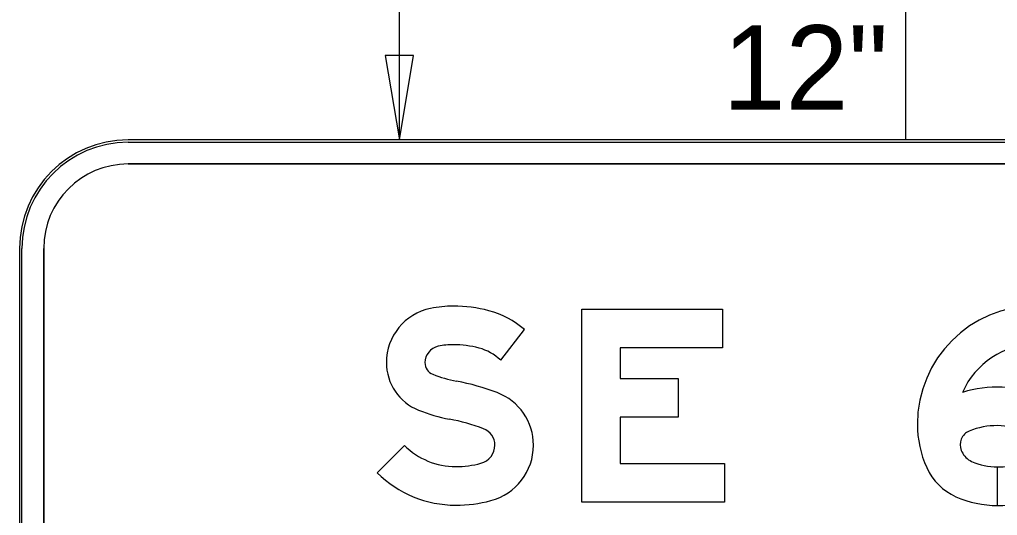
# Model space of a CAD drawing. Extents: x 2149934 to 2150188, y 145113 to 145238.
# Drawn here: x 2150088.03 to 2150094.79, y 145200.85 to 145204.28 of the extents above; entities that cross this region are included whole.
import ezdxf

# ---------------------------------------------------------------- set-up
doc = ezdxf.new("R2010")
doc.units = 0
for name, color, linetype in [('GSBWFILL', 7, 'Continuous'), ('GSCOLORFILL', 7, 'Continuous'), ('GSDIMS', 7, 'Continuous'), ('GSOUTLINE', 7, 'Continuous')]:
    doc.layers.add(name, color=color, linetype=linetype)

msp = doc.modelspace()

# ---------------------------------------------------------------- linework, layer by layer
at = {"layer": 'GSBWFILL'}
for p, q in [((2150107.2786, 145203.4449), (2150088.7786, 145203.4449)), ((2150088.7786, 145203.2782), (2150107.2786, 145203.2782)), ((2150088.0286, 145202.6949), (2150088.0286, 145198.1946)), ((2150088.1953, 145198.1946), (2150088.1953, 145202.6949))]:
    msp.add_line(p, q, dxfattribs=at)
msp.add_lwpolyline([(2150092.8872, 145202.2755), (2150092.8872, 145202.0088), (2150092.1805, 145202.0088), (2150092.1805, 145201.7955), (2150092.5805, 145201.7955), (2150092.5805, 145201.5288), (2150092.1805, 145201.5288), (2150092.1805, 145201.2088), (2150092.9005, 145201.2088), (2150092.9005, 145200.9421), (2150091.9139, 145200.9421), (2150091.9139, 145202.2755)], close=True, dxfattribs=at)
for points in [[(2150091.3539, 145201.9235), (2150091.5188, 145202.134)], [(2150090.6883, 145201.334), (2150090.5005, 145201.1446)], [(2150094.7873, 145200.9188), (2150094.7873, 145201.1855)]]:
    msp.add_lwpolyline(points, dxfattribs=at)
for radius in [0.75, 0.5833]:
    msp.add_arc((2150088.7786, 145202.6949), radius, 90, 180, dxfattribs=at)
for centre, major_axis, ratio, start_param, end_param in [((2150090.9459, 145201.9063), (0, 0.382), 0.999996, 0.202758, 1.570796), ((2150091.0272, 145201.511), (0, 0.7855), 0.999996, 0, 0.202758), ((2150091.0272, 145201.3333), (0, 0.9632), 0.999996, 6.026234, 6.283185), ((2150091.1165, 145201.6734), (0, 0.6115), 0.999996, 5.565152, 6.026234), ((2150095.0519, 145201.4808), (0, 0.818), 0.999998, 0, 1.570796), ((2150090.9459, 145201.9063), (0, 0.1153), 0.999996, 0.202758, 1.570796), ((2150091.0272, 145201.511), (0, 0.5188), 0.999996, 0, 0.202758), ((2150091.0272, 145201.3333), (0, 0.6965), 0.999996, 6.026234, 6.283185), ((2150091.1165, 145201.6734), (0, 0.3448), 0.999996, 5.523837, 6.026234), ((2150095.0519, 145201.4808), (0, 0.5514), 0.999998, 0, 1.161745), ((2150090.9178, 145201.9063), (0, 0.3538), 0.999996, 1.570796, 2.761249), ((2150090.9178, 145201.9063), (0, 0.0872), 0.999996, 1.570796, 2.761249), ((2150091.2084, 145202.6331), (0, 0.8699), 0.999996, 2.761249, 2.95744), ((2150090.7518, 145200.182), (0, 1.6233), 0.999996, 5.918637, 6.099033), ((2150094.783, 145200.9689), (0, 0.7686), 0.999998, 5.875072, 6.596573), ((2150091.1921, 145201.3357), (0, 0.3885), 0.999996, 4.712389, 5.918637), ((2150091.2084, 145202.6331), (0, 1.1366), 0.999996, 2.761249, 2.95744), ((2150090.7518, 145200.182), (0, 1.3566), 0.999996, 5.918637, 6.099033), ((2150091.1921, 145201.3357), (0, 0.1218), 0.999996, 4.712389, 5.918637), ((2150094.9615, 145201.4808), (0, 0.7277), 0.999998, 1.570796, 1.996105), ((2150094.783, 145200.9689), (0, 0.502), 0.999998, 5.875072, 6.672982), ((2150094.6307, 145201.3395), (0, 0.1013), 0.999998, 0.389797, 1.974401), ((2150091.0434, 145201.6923), (0, 0.5044), 0.999996, 2.360607, 3.141593), ((2150091.1844, 145201.3357), (0, 0.1295), 0.999996, 3.401517, 4.712389), ((2150091.1844, 145201.3357), (0, 0.3961), 0.999996, 3.401517, 4.712389), ((2150094.9615, 145201.4808), (0, 0.461), 0.999998, 1.974401, 1.996105), ((2150094.6638, 145201.3459), (0, 0.1341), 0.999998, 1.996105, 2.721836), ((2150091.0434, 145201.866), (0, 0.6782), 0.999996, 3.141593, 3.401517), ((2150094.6638, 145201.3459), (0, 0.4008), 0.999998, 1.996105, 2.721836), ((2150094.7873, 145201.6227), (0, 0.4372), 0.999998, 2.721836, 3.141593), ((2150091.0434, 145201.6923), (0, 0.7711), 0.999996, 2.360607, 3.141593), ((2150094.7873, 145201.6227), (0, 0.7039), 0.999998, 2.721836, 3.141593), ((2150091.0434, 145201.866), (0, 0.9449), 0.999996, 3.141593, 3.401517)]:
    msp.add_ellipse(centre, major_axis=major_axis, ratio=ratio, start_param=start_param, end_param=end_param, dxfattribs=at)
at = {"layer": 'GSCOLORFILL'}
for p, q in [((2150107.2786, 145203.4449), (2150088.7786, 145203.4449)), ((2150107.2786, 145203.4449), (2150088.7786, 145203.4449)), ((2150107.2786, 145203.4449), (2150088.7786, 145203.4449)), ((2150088.7786, 145203.4282), (2150107.2786, 145203.4282)), ((2150088.7786, 145203.2782), (2150107.2786, 145203.2782)), ((2150088.0286, 145202.6949), (2150088.0286, 145198.1946)), ((2150088.0286, 145202.6949), (2150088.0286, 145198.1946)), ((2150088.0286, 145202.6949), (2150088.0286, 145198.1946)), ((2150088.0453, 145198.1946), (2150088.0453, 145202.6949)), ((2150088.1953, 145198.1946), (2150088.1953, 145202.6949))]:
    msp.add_line(p, q, dxfattribs=at)
msp.add_lwpolyline([(2150092.8872, 145202.2755), (2150092.8872, 145202.0088), (2150092.1805, 145202.0088), (2150092.1805, 145201.7955), (2150092.5805, 145201.7955), (2150092.5805, 145201.5288), (2150092.1805, 145201.5288), (2150092.1805, 145201.2088), (2150092.9005, 145201.2088), (2150092.9005, 145200.9421), (2150091.9139, 145200.9421), (2150091.9139, 145202.2755)], close=True, dxfattribs=at)
for points in [[(2150091.3539, 145201.9235), (2150091.5188, 145202.134)], [(2150090.6883, 145201.334), (2150090.5005, 145201.1446)], [(2150094.7873, 145200.9188), (2150094.7873, 145201.1855)]]:
    msp.add_lwpolyline(points, dxfattribs=at)
for radius in [0.75, 0.75, 0.75, 0.7333, 0.5833]:
    msp.add_arc((2150088.7786, 145202.6949), radius, 90, 180, dxfattribs=at)
for centre, major_axis, ratio, start_param, end_param in [((2150090.9459, 145201.9063), (0, 0.382), 0.999996, 0.202758, 1.570796), ((2150091.0272, 145201.511), (0, 0.7855), 0.999996, 0, 0.202758), ((2150091.0272, 145201.3333), (0, 0.9632), 0.999996, 6.026234, 6.283185), ((2150091.1165, 145201.6734), (0, 0.6115), 0.999996, 5.565152, 6.026234), ((2150095.0519, 145201.4808), (0, 0.818), 0.999998, 0, 1.570796), ((2150090.9459, 145201.9063), (0, 0.1153), 0.999996, 0.202758, 1.570796), ((2150091.0272, 145201.511), (0, 0.5188), 0.999996, 0, 0.202758), ((2150091.0272, 145201.3333), (0, 0.6965), 0.999996, 6.026234, 6.283185), ((2150091.1165, 145201.6734), (0, 0.3448), 0.999996, 5.523837, 6.026234), ((2150095.0519, 145201.4808), (0, 0.5514), 0.999998, 0, 1.161745), ((2150090.9178, 145201.9063), (0, 0.3538), 0.999996, 1.570796, 2.761249), ((2150090.9178, 145201.9063), (0, 0.0872), 0.999996, 1.570796, 2.761249), ((2150091.2084, 145202.6331), (0, 0.8699), 0.999996, 2.761249, 2.95744), ((2150090.7518, 145200.182), (0, 1.6233), 0.999996, 5.918637, 6.099033), ((2150094.783, 145200.9689), (0, 0.7686), 0.999998, 5.875072, 6.596573), ((2150091.1921, 145201.3357), (0, 0.3885), 0.999996, 4.712389, 5.918637), ((2150091.2084, 145202.6331), (0, 1.1366), 0.999996, 2.761249, 2.95744), ((2150090.7518, 145200.182), (0, 1.3566), 0.999996, 5.918637, 6.099033), ((2150091.1921, 145201.3357), (0, 0.1218), 0.999996, 4.712389, 5.918637), ((2150094.9615, 145201.4808), (0, 0.7277), 0.999998, 1.570796, 1.996105), ((2150094.783, 145200.9689), (0, 0.502), 0.999998, 5.875072, 6.672982), ((2150094.6307, 145201.3395), (0, 0.1013), 0.999998, 0.389797, 1.974401), ((2150091.0434, 145201.6923), (0, 0.5044), 0.999996, 2.360607, 3.141593), ((2150091.1844, 145201.3357), (0, 0.1295), 0.999996, 3.401517, 4.712389), ((2150091.1844, 145201.3357), (0, 0.3961), 0.999996, 3.401517, 4.712389), ((2150094.9615, 145201.4808), (0, 0.461), 0.999998, 1.974401, 1.996105), ((2150094.6638, 145201.3459), (0, 0.1341), 0.999998, 1.996105, 2.721836), ((2150091.0434, 145201.866), (0, 0.6782), 0.999996, 3.141593, 3.401517), ((2150094.6638, 145201.3459), (0, 0.4008), 0.999998, 1.996105, 2.721836), ((2150094.7873, 145201.6227), (0, 0.4372), 0.999998, 2.721836, 3.141593), ((2150091.0434, 145201.6923), (0, 0.7711), 0.999996, 2.360607, 3.141593), ((2150094.7873, 145201.6227), (0, 0.7039), 0.999998, 2.721836, 3.141593), ((2150091.0434, 145201.866), (0, 0.9449), 0.999996, 3.141593, 3.401517)]:
    msp.add_ellipse(centre, major_axis=major_axis, ratio=ratio, start_param=start_param, end_param=end_param, dxfattribs=at)
at = {"layer": 'GSDIMS'}
for p, q in [((2150090.6535, 145203.4448), (2150090.6535, 145206.4452)), ((2150094.1535, 145203.4448), (2150094.1535, 145204.4451)), ((2150091.091, 145203.4448), (2150090.3618, 145203.4448)), ((2150094.591, 145203.4448), (2150091.091, 145203.4448)), ((2150094.591, 145203.4448), (2150093.8618, 145203.4448))]:
    msp.add_line(p, q, dxfattribs=at)
msp.add_lwpolyline([(2150090.6535, 145203.4448), (2150090.7507, 145204.0281), (2150090.5563, 145204.0281)], close=True, dxfattribs=at)
at = {"layer": 'GSOUTLINE'}
for p, q in [((2150107.2786, 145203.4449), (2150088.7786, 145203.4449)), ((2150107.2786, 145203.2782), (2150088.7786, 145203.2782)), ((2150088.0286, 145202.6949), (2150088.0286, 145198.1946)), ((2150088.1953, 145202.6949), (2150088.1953, 145198.1946))]:
    msp.add_line(p, q, dxfattribs=at)
msp.add_lwpolyline([(2150092.8872, 145202.2755), (2150092.8872, 145202.0088), (2150092.1805, 145202.0088), (2150092.1805, 145201.7955), (2150092.5805, 145201.7955), (2150092.5805, 145201.5288), (2150092.1805, 145201.5288), (2150092.1805, 145201.2088), (2150092.9005, 145201.2088), (2150092.9005, 145200.9421), (2150091.9139, 145200.9421), (2150091.9139, 145202.2755)], close=True, dxfattribs=at)
for points in [[(2150091.3539, 145201.9235), (2150091.5188, 145202.134)], [(2150090.6883, 145201.334), (2150090.5005, 145201.1446)]]:
    msp.add_lwpolyline(points, dxfattribs=at)
for radius in [0.75, 0.5833]:
    msp.add_arc((2150088.7786, 145202.6949), radius, 90, 180, dxfattribs=at)
for centre, major_axis, ratio, start_param, end_param in [((2150090.9459, 145201.9063), (0, 0.382), 0.999996, 0.202758, 1.570796), ((2150091.0272, 145201.511), (0, 0.7855), 0.999996, 0, 0.202758), ((2150091.0272, 145201.3333), (0, 0.9632), 0.999996, 6.026234, 6.283185), ((2150091.1165, 145201.6734), (0, 0.6115), 0.999996, 5.565152, 6.026234), ((2150095.0519, 145201.4808), (0, 0.818), 0.999998, 0, 1.570796), ((2150090.9459, 145201.9063), (0, 0.1153), 0.999996, 0.202758, 1.570796), ((2150091.0272, 145201.511), (0, 0.5188), 0.999996, 0, 0.202758), ((2150091.0272, 145201.3333), (0, 0.6965), 0.999996, 6.026234, 6.283185), ((2150091.1165, 145201.6734), (0, 0.3448), 0.999996, 5.523837, 6.026234), ((2150095.0519, 145201.4808), (0, 0.5514), 0.999998, 0, 1.161745), ((2150090.9178, 145201.9063), (0, 0.3538), 0.999996, 1.570796, 2.761249), ((2150090.9178, 145201.9063), (0, 0.0872), 0.999996, 1.570796, 2.761249), ((2150091.2084, 145202.6331), (0, 0.8699), 0.999996, 2.761249, 2.95744), ((2150090.7518, 145200.182), (0, 1.6233), 0.999996, 5.918637, 6.099033), ((2150094.783, 145200.9689), (0, 0.7686), 0.999998, 5.875072, 6.596573), ((2150091.1921, 145201.3357), (0, 0.3885), 0.999996, 4.712389, 5.918637), ((2150091.2084, 145202.6331), (0, 1.1366), 0.999996, 2.761249, 2.95744), ((2150090.7518, 145200.182), (0, 1.3566), 0.999996, 5.918637, 6.099033), ((2150091.1921, 145201.3357), (0, 0.1218), 0.999996, 4.712389, 5.918637), ((2150094.9615, 145201.4808), (0, 0.7277), 0.999998, 1.570796, 1.996105), ((2150094.783, 145200.9689), (0, 0.502), 0.999998, 5.875072, 6.672982), ((2150094.6307, 145201.3395), (0, 0.1013), 0.999998, 0.389797, 1.974401), ((2150091.0434, 145201.6923), (0, 0.5044), 0.999996, 2.360607, 3.141593), ((2150091.1844, 145201.3357), (0, 0.1295), 0.999996, 3.401517, 4.712389), ((2150091.1844, 145201.3357), (0, 0.3961), 0.999996, 3.401517, 4.712389), ((2150094.9615, 145201.4808), (0, 0.461), 0.999998, 1.974401, 1.996105), ((2150094.6638, 145201.3459), (0, 0.1341), 0.999998, 1.996105, 2.721836), ((2150091.0434, 145201.866), (0, 0.6782), 0.999996, 3.141593, 3.401517), ((2150094.6638, 145201.3459), (0, 0.4008), 0.999998, 1.996105, 2.721836), ((2150094.7873, 145201.6227), (0, 0.4372), 0.999998, 2.721836, 3.141593), ((2150094.7873, 145201.7879), (0, 0.6024), 0.999998, 3.141593, 3.228955), ((2150091.0434, 145201.6923), (0, 0.7711), 0.999996, 2.360607, 3.141593), ((2150094.7873, 145201.6227), (0, 0.7039), 0.999998, 2.721836, 3.141593), ((2150091.0434, 145201.866), (0, 0.9449), 0.999996, 3.141593, 3.401517), ((2150094.7873, 145201.7879), (0, 0.8691), 0.999998, 3.141593, 3.228955)]:
    msp.add_ellipse(centre, major_axis=major_axis, ratio=ratio, start_param=start_param, end_param=end_param, dxfattribs=at)

# ---------------------------------------------------------------- texts
at = {"layer": 'GSDIMS'}
msp.add_text('12"', height=0.58333, dxfattribs=at).set_placement((2150092.8887, 145203.6533))

doc.saveas('drawing.dxf')
